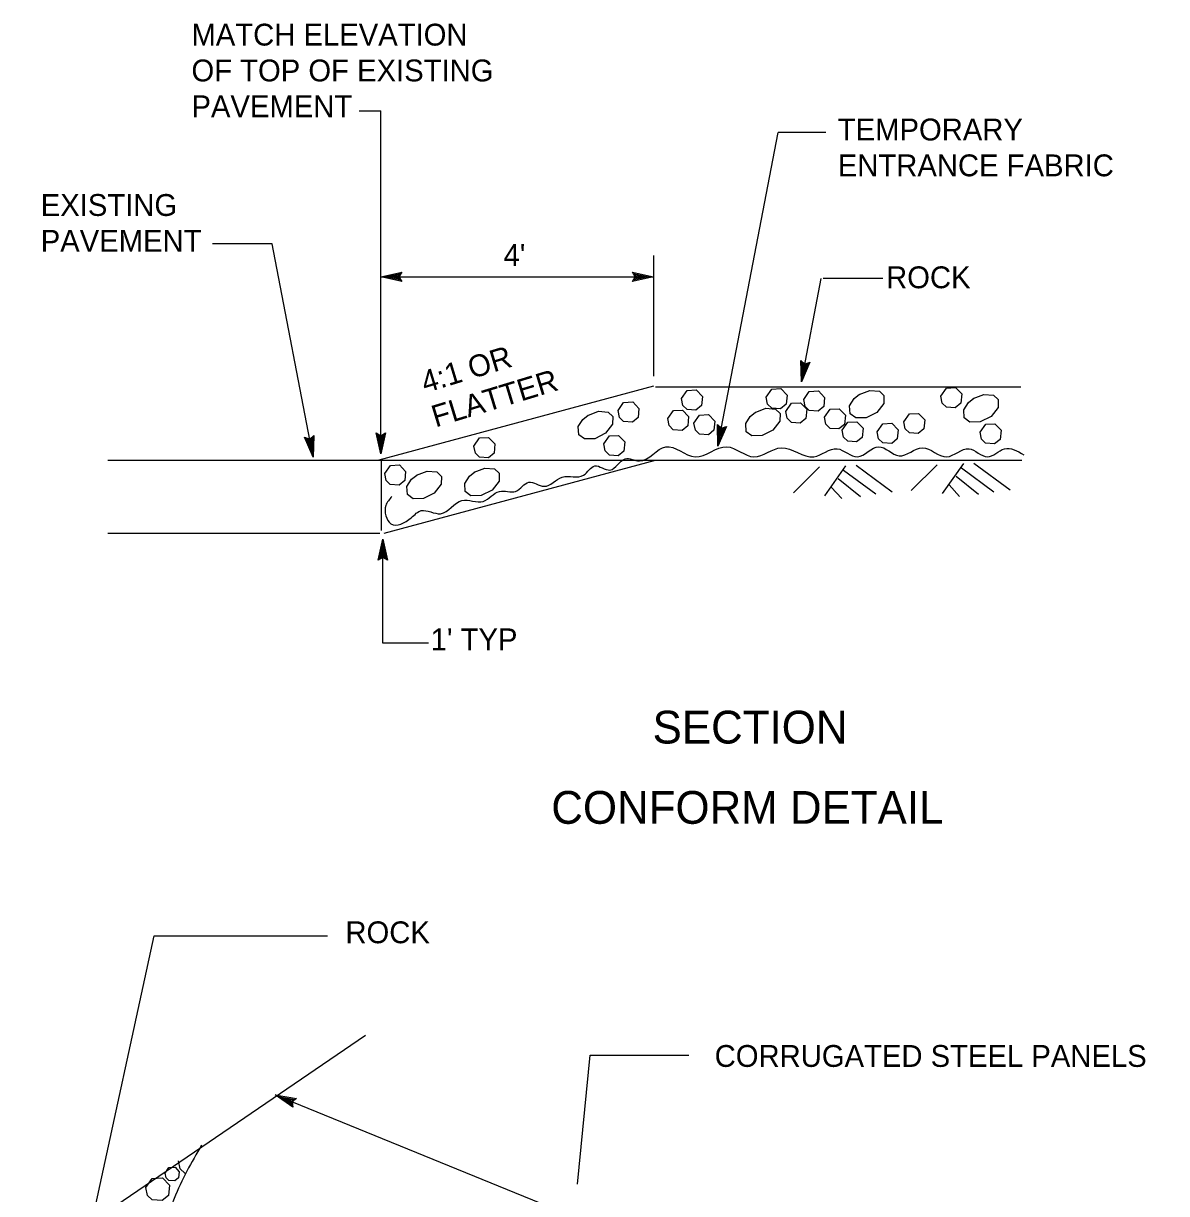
# Model space of a CAD drawing. Extents: x 6709491 to 6710959, y 1869789 to 1870763.
# Drawn here: x 6709790.5 to 6710104.3, y 1870437.5 to 1870758.8 of the extents above; entities that cross this region are included whole.
import ezdxf

# ---------------------------------------------------------------- set-up
doc = ezdxf.new("R2010")
doc.units = 0
for name, color, linetype in [('56 Stg 3 Anno', 7, 'Continuous'), ('57 Undefined', 7, 'Continuous'), ('59 Soundwall Ann', 7, 'Continuous'), ('60 Nongeo Data', 7, 'Continuous')]:
    doc.layers.add(name, color=color, linetype=linetype)

msp = doc.modelspace()

# ---------------------------------------------------------------- linework, layer by layer
at = {"layer": '56 Stg 3 Anno'}
for p, q in [((6709882.69, 1870734.85), (6709888.58, 1870734.85)), ((6709888.58, 1870640.62), (6709888.58, 1870734.85)), ((6709981.16, 1870642.76), (6709997.7, 1870728.84)), ((6710010.8, 1870728.84), (6709997.7, 1870728.84)), ((6709858.77, 1870698.25), (6709842.43, 1870698.25)), ((6709870.01, 1870639.76), (6709858.77, 1870698.25)), ((6709963.41, 1870695.06), (6709963.41, 1870661.92)), ((6709888.58, 1870689.24), (6709894.34, 1870690.52)), ((6709889.92, 1870689.24), (6709894.12, 1870690.17)), ((6709894.34, 1870690.52), (6709893.58, 1870689.24)), ((6709894.34, 1870690.52), (6709894.34, 1870690.52)), ((6709958.42, 1870689.24), (6709957.65, 1870690.53)), ((6709957.65, 1870690.53), (6709957.65, 1870690.53)), ((6709957.65, 1870690.53), (6709963.41, 1870689.24)), ((6709957.86, 1870690.19), (6709962.09, 1870689.24)), ((6709888.58, 1870689.24), (6709963.41, 1870689.24)), ((6709894.34, 1870687.95), (6709888.58, 1870689.24)), ((6709888.58, 1870689.24), (6709888.58, 1870689.24)), ((6709894.14, 1870688.3), (6709889.91, 1870689.24)), ((6709891.24, 1870689.24), (6709893.95, 1870689.84)), ((6709893.91, 1870688.64), (6709891.24, 1870689.24)), ((6709892.56, 1870689.24), (6709893.72, 1870689.49)), ((6709893.74, 1870688.97), (6709892.56, 1870689.24)), ((6709893.58, 1870689.24), (6709894.34, 1870687.95)), ((6709894.34, 1870687.95), (6709894.34, 1870687.95)), ((6709963.41, 1870689.24), (6709957.65, 1870687.96)), ((6709957.65, 1870687.96), (6709958.42, 1870689.24)), ((6709957.65, 1870687.96), (6709957.65, 1870687.96)), ((6709962.08, 1870689.24), (6709957.88, 1870688.31)), ((6709960.76, 1870689.24), (6709958.05, 1870688.64)), ((6709958.09, 1870689.84), (6709960.76, 1870689.24)), ((6709958.26, 1870689.51), (6709959.44, 1870689.24)), ((6709959.44, 1870689.24), (6709958.27, 1870688.99)), ((6709963.41, 1870689.24), (6709963.41, 1870689.24)), ((6710004.04, 1870660.38), (6710009.5, 1870688.77)), ((6710026.4, 1870688.77), (6710010.05, 1870688.77)), ((6710004.04, 1870660.38), (6710003.87, 1870666.28)), ((6710003.87, 1870666.28), (6710003.87, 1870666.28)), ((6710003.87, 1870666.28), (6710004.98, 1870665.28)), ((6710006.39, 1870665.79), (6710004.04, 1870660.38)), ((6710004.29, 1870661.69), (6710004.17, 1870665.99)), ((6710006.02, 1870665.65), (6710004.29, 1870661.68)), ((6710004.54, 1870662.98), (6710004.46, 1870665.76)), ((6710005.63, 1870665.5), (6710004.54, 1870662.98)), ((6710004.79, 1870664.28), (6710004.76, 1870665.47)), ((6710005.28, 1870665.39), (6710004.79, 1870664.28)), ((6710004.98, 1870665.28), (6710006.39, 1870665.79)), ((6710006.39, 1870665.79), (6710006.39, 1870665.79)), ((6710004.04, 1870660.38), (6710004.04, 1870660.38)), ((6709981.16, 1870642.76), (6709981, 1870648.65)), ((6709981, 1870648.65), (6709981, 1870648.65)), ((6709981, 1870648.65), (6709982.1, 1870647.66)), ((6709981.41, 1870644.07), (6709981.29, 1870648.37)), ((6709870.01, 1870639.76), (6709867.67, 1870645.17)), ((6709867.67, 1870645.17), (6709867.67, 1870645.17)), ((6709867.67, 1870645.17), (6709869.07, 1870644.66)), ((6709869.07, 1870644.66), (6709870.19, 1870645.66)), ((6709869.59, 1870645.1), (6709869.51, 1870642.36)), ((6709869.89, 1870645.39), (6709869.76, 1870641.06)), ((6709870.19, 1870645.66), (6709870.01, 1870639.76)), ((6709870.19, 1870645.66), (6709870.19, 1870645.66)), ((6709888.58, 1870640.62), (6709887.31, 1870646.38)), ((6709887.31, 1870646.38), (6709887.31, 1870646.38)), ((6709887.31, 1870646.38), (6709888.58, 1870645.61)), ((6709888.58, 1870641.95), (6709887.65, 1870646.15)), ((6709888.59, 1870643.27), (6709887.98, 1870645.98)), ((6709888.59, 1870644.6), (6709888.33, 1870645.76)), ((6709888.58, 1870645.61), (6709889.87, 1870646.38)), ((6709889.87, 1870646.38), (6709888.58, 1870640.62)), ((6709889.53, 1870646.17), (6709888.58, 1870641.94)), ((6709889.18, 1870645.94), (6709888.59, 1870643.27)), ((6709888.85, 1870645.78), (6709888.59, 1870644.6)), ((6709889.87, 1870646.38), (6709889.87, 1870646.38)), ((6709983.51, 1870648.17), (6709981.16, 1870642.76)), ((6709983.14, 1870648.03), (6709981.41, 1870644.06)), ((6709981.67, 1870645.36), (6709981.59, 1870648.14)), ((6709982.76, 1870647.88), (6709981.67, 1870645.36)), ((6709981.92, 1870646.66), (6709981.88, 1870647.85)), ((6709982.4, 1870647.77), (6709981.92, 1870646.66)), ((6709982.1, 1870647.66), (6709983.51, 1870648.17)), ((6709983.51, 1870648.17), (6709983.51, 1870648.17)), ((6709869.76, 1870641.07), (6709868.05, 1870645.02)), ((6709869.51, 1870642.36), (6709868.41, 1870644.91)), ((6709869.26, 1870643.67), (6709868.79, 1870644.76)), ((6709869.3, 1870644.88), (6709869.26, 1870643.67)), ((6709981.16, 1870642.76), (6709981.16, 1870642.76)), ((6709870.01, 1870639.76), (6709870.01, 1870639.76)), ((6709888.58, 1870640.62), (6709888.58, 1870640.62)), ((6709887.85, 1870611.42), (6709889.14, 1870617.18)), ((6709889.14, 1870588.65), (6709889.14, 1870617.18)), ((6709889.14, 1870617.18), (6709889.14, 1870617.18)), ((6709889.14, 1870617.18), (6709890.42, 1870611.42)), ((6709888.2, 1870611.63), (6709889.14, 1870615.86)), ((6709888.54, 1870611.86), (6709889.14, 1870614.53)), ((6709888.87, 1870612.03), (6709889.14, 1870613.21)), ((6709889.14, 1870615.85), (6709890.07, 1870611.65)), ((6709889.14, 1870614.53), (6709889.74, 1870611.82)), ((6709889.14, 1870613.21), (6709889.39, 1870612.05)), ((6709889.14, 1870612.19), (6709887.85, 1870611.42)), ((6709887.85, 1870611.42), (6709887.85, 1870611.42)), ((6709890.42, 1870611.42), (6709889.14, 1870612.19)), ((6709890.42, 1870611.42), (6709890.42, 1870611.42)), ((6709901.67, 1870588.65), (6709889.14, 1870588.65)), ((6709803.25, 1870401.82), (6709826.34, 1870508.28)), ((6709826.34, 1870508.28), (6709873.95, 1870508.28)), ((6709942.55, 1870440.07), (6709946.04, 1870475.53)), ((6709946.04, 1870475.53), (6709973.16, 1870475.53)), ((6709859.63, 1870464.61), (6710181.3, 1870333.54)), ((6709864.48, 1870461.25), (6709859.63, 1870464.61)), ((6709859.63, 1870464.61), (6709859.63, 1870464.61)), ((6709859.63, 1870464.61), (6709865.45, 1870463.62)), ((6709864.42, 1870461.64), (6709860.86, 1870464.11)), ((6709860.87, 1870464.11), (6709865.11, 1870463.39)), ((6709864.34, 1870462.05), (6709862.09, 1870463.61)), ((6709862.09, 1870463.61), (6709864.83, 1870463.14)), ((6709864.31, 1870462.42), (6709863.32, 1870463.11)), ((6709863.32, 1870463.11), (6709864.49, 1870462.91)), ((6709865.45, 1870463.62), (6709864.26, 1870462.73)), ((6709864.26, 1870462.73), (6709864.48, 1870461.25)), ((6709865.45, 1870463.62), (6709865.45, 1870463.62)), ((6709864.48, 1870461.25), (6709864.48, 1870461.25))]:
    msp.add_line(p, q, dxfattribs=at)
at = {"layer": '59 Soundwall Ann'}
for p, q in [((6710009.02, 1870637.04), (6710001.85, 1870629.93)), ((6710016.17, 1870637.38), (6710010.38, 1870629.14)), ((6710015.62, 1870636.16), (6710024.52, 1870629.61)), ((6710019.07, 1870637.51), (6710029.02, 1870630.18)), ((6710041.37, 1870637.64), (6710034.2, 1870630.53)), ((6710048.52, 1870637.98), (6710042.74, 1870629.74)), ((6710047.97, 1870636.76), (6710056.87, 1870630.21)), ((6710051.42, 1870638.11), (6710061.38, 1870630.78)), ((6710014.18, 1870633.9), (6710020.29, 1870628.92)), ((6710046.53, 1870634.5), (6710052.64, 1870629.52)), ((6710012.24, 1870631.52), (6710015.15, 1870628.32)), ((6710044.59, 1870632.11), (6710047.5, 1870628.92))]:
    msp.add_line(p, q, dxfattribs=at)
at = {"layer": '60 Nongeo Data'}
for p, q in [((6709888.11, 1870638.95), (6709963.56, 1870659.27)), ((6709964.03, 1870658.99), (6710064.27, 1870658.99)), ((6709813.68, 1870638.93), (6709888.86, 1870638.93)), ((6709888.67, 1870638.97), (6709888.67, 1870619.57)), ((6709888.86, 1870638.93), (6709964.59, 1870638.93)), ((6709889.53, 1870618.87), (6709964.03, 1870638.93)), ((6709964.03, 1870638.93), (6710064.55, 1870638.93)), ((6709813.68, 1870618.87), (6709888.3, 1870618.87)), ((6709495.94, 1870216.26), (6709884.38, 1870481.01))]:
    msp.add_line(p, q, dxfattribs=at)
for points in [[(6709971.13, 1870655.85), (6709972.68, 1870658.05), (6709975.15, 1870658.19), (6709976.87, 1870656.41), (6709976.62, 1870653.91), (6709975.1, 1870652.64), (6709972.65, 1870652.82), (6709971.5, 1870653.93), (6709971.13, 1870655.85)], [(6709994.38, 1870656.22), (6709995.93, 1870658.43), (6709998.41, 1870658.57), (6710000.13, 1870656.78), (6709999.88, 1870654.28), (6709998.35, 1870653.01), (6709995.91, 1870653.19), (6709994.76, 1870654.3), (6709994.39, 1870656.22)], [(6710019.9, 1870656.91), (6710022.8, 1870658.05), (6710025.46, 1870657.82), (6710026.73, 1870656.62), (6710026.69, 1870654.46), (6710024.77, 1870652), (6710021.8, 1870650.52), (6710019, 1870650.47), (6710017.42, 1870651.59), (6710017.27, 1870653.82), (6710018.55, 1870655.81), (6710020.02, 1870656.98)], [(6710042.34, 1870656.49), (6710043.89, 1870658.7), (6710046.36, 1870658.84), (6710048.08, 1870657.06), (6710047.84, 1870654.55), (6710046.31, 1870653.28), (6710043.86, 1870653.46), (6710042.71, 1870654.58), (6710042.34, 1870656.49)], [(6709953.71, 1870652.52), (6709955.26, 1870654.73), (6709957.74, 1870654.87), (6709959.46, 1870653.09), (6709959.21, 1870650.59), (6709957.68, 1870649.31), (6709955.23, 1870649.49), (6709954.08, 1870650.61), (6709953.71, 1870652.52)], [(6710004.68, 1870655.56), (6710006.23, 1870657.76), (6710008.71, 1870657.9), (6710010.43, 1870656.12), (6710010.18, 1870653.62), (6710008.65, 1870652.35), (6710006.21, 1870652.52), (6710005.06, 1870653.64), (6710004.68, 1870655.55)], [(6710051.24, 1870655.8), (6710054.14, 1870656.95), (6710056.8, 1870656.72), (6710058.07, 1870655.51), (6710058.03, 1870653.35), (6710056.11, 1870650.9), (6710053.14, 1870649.41), (6710050.34, 1870649.36), (6710048.76, 1870650.48), (6710048.62, 1870652.71), (6710049.89, 1870654.7), (6710051.36, 1870655.87)], [(6709945.44, 1870651.18), (6709948.34, 1870652.33), (6709951, 1870652.09), (6709952.27, 1870650.89), (6709952.23, 1870648.73), (6709950.3, 1870646.27), (6709947.33, 1870644.79), (6709944.54, 1870644.74), (6709942.96, 1870645.86), (6709942.81, 1870648.09), (6709944.09, 1870650.08), (6709945.55, 1870651.25)], [(6709967.35, 1870650.29), (6709968.9, 1870652.5), (6709971.38, 1870652.64), (6709973.1, 1870650.86), (6709972.85, 1870648.36), (6709971.32, 1870647.08), (6709968.88, 1870647.26), (6709967.73, 1870648.38), (6709967.36, 1870650.29)], [(6709991.38, 1870652.01), (6709994.28, 1870653.16), (6709996.94, 1870652.93), (6709998.21, 1870651.73), (6709998.17, 1870649.57), (6709996.25, 1870647.11), (6709993.28, 1870645.62), (6709990.48, 1870645.58), (6709988.9, 1870646.69), (6709988.76, 1870648.92), (6709990.03, 1870650.92), (6709991.5, 1870652.09)], [(6709999.79, 1870652.29), (6710001.34, 1870654.5), (6710003.82, 1870654.64), (6710005.54, 1870652.86), (6710005.29, 1870650.36), (6710003.76, 1870649.08), (6710001.32, 1870649.26), (6710000.17, 1870650.38), (6709999.79, 1870652.29)], [(6710010.39, 1870650.66), (6710011.94, 1870652.87), (6710014.41, 1870653.01), (6710016.13, 1870651.22), (6710015.88, 1870648.72), (6710014.35, 1870647.45), (6710011.91, 1870647.63), (6710010.76, 1870648.75), (6710010.39, 1870650.66)], [(6710032.17, 1870649.41), (6710033.73, 1870651.61), (6710036.2, 1870651.75), (6710037.92, 1870649.97), (6710037.67, 1870647.47), (6710036.14, 1870646.2), (6710033.7, 1870646.37), (6710032.55, 1870647.49), (6710032.18, 1870649.4)], [(6709974.57, 1870649.07), (6709976.12, 1870651.28), (6709978.59, 1870651.42), (6709980.31, 1870649.64), (6709980.06, 1870647.13), (6709978.54, 1870645.86), (6709976.09, 1870646.04), (6709974.94, 1870647.16), (6709974.57, 1870649.07)], [(6710015.24, 1870647.1), (6710016.79, 1870649.31), (6710019.27, 1870649.45), (6710020.98, 1870647.66), (6710020.74, 1870645.16), (6710019.21, 1870643.89), (6710016.76, 1870644.07), (6710015.61, 1870645.18), (6710015.24, 1870647.1)], [(6710024.88, 1870646.67), (6710026.43, 1870648.87), (6710028.9, 1870649.02), (6710030.62, 1870647.23), (6710030.37, 1870644.73), (6710028.85, 1870643.46), (6710026.4, 1870643.64), (6710025.25, 1870644.75), (6710024.88, 1870646.67)], [(6710053.12, 1870646.55), (6710054.67, 1870648.75), (6710057.14, 1870648.9), (6710058.86, 1870647.11), (6710058.62, 1870644.61), (6710057.09, 1870643.34), (6710054.64, 1870643.52), (6710053.49, 1870644.63), (6710053.12, 1870646.55)], [(6709914.17, 1870642.77), (6709915.72, 1870644.98), (6709918.2, 1870645.12), (6709919.92, 1870643.33), (6709919.67, 1870640.83), (6709918.14, 1870639.56), (6709915.69, 1870639.74), (6709914.55, 1870640.85), (6709914.17, 1870642.77)], [(6709949.81, 1870643.33), (6709951.36, 1870645.53), (6709953.84, 1870645.67), (6709955.56, 1870643.89), (6709955.31, 1870641.39), (6709953.78, 1870640.12), (6709951.34, 1870640.3), (6709950.19, 1870641.41), (6709949.81, 1870643.33)], [(6709889.67, 1870635.25), (6709891.22, 1870637.45), (6709893.69, 1870637.59), (6709895.41, 1870635.81), (6709895.16, 1870633.31), (6709893.64, 1870632.04), (6709891.19, 1870632.22), (6709890.04, 1870633.33), (6709889.67, 1870635.25)], [(6709898.38, 1870634.74), (6709901.28, 1870635.89), (6709903.94, 1870635.66), (6709905.21, 1870634.45), (6709905.17, 1870632.29), (6709903.25, 1870629.83), (6709900.28, 1870628.35), (6709897.48, 1870628.3), (6709895.9, 1870629.42), (6709895.76, 1870631.65), (6709897.03, 1870633.64), (6709898.5, 1870634.81)], [(6709914.25, 1870635.57), (6709917.15, 1870636.72), (6709919.82, 1870636.49), (6709921.08, 1870635.29), (6709921.04, 1870633.13), (6709919.12, 1870630.67), (6709916.15, 1870629.19), (6709913.35, 1870629.14), (6709911.78, 1870630.26), (6709911.63, 1870632.48), (6709912.9, 1870634.48), (6709914.37, 1870635.65)], [(6709834.9, 1870443.07), (6709834.76, 1870443.08), (6709833.47, 1870444.33), (6709833.05, 1870446.48)], [(6709829.39, 1870443.15), (6709830.43, 1870444.64), (6709832.1, 1870444.73), (6709833.25, 1870443.53), (6709833.09, 1870441.85), (6709832.06, 1870440.99), (6709830.41, 1870441.11), (6709829.64, 1870441.86), (6709829.39, 1870443.15)], [(6709824.11, 1870439.17), (6709825.85, 1870441.64), (6709828.62, 1870441.8), (6709830.56, 1870439.8), (6709830.28, 1870437), (6709828.56, 1870435.57), (6709825.82, 1870435.77), (6709824.53, 1870437.02), (6709824.11, 1870439.17)]]:
    msp.add_lwpolyline(points, dxfattribs=at)
for points in [[(6709891.64, 1870628.94), (6709889.97, 1870626.43), (6709889.97, 1870623.64), (6709891.36, 1870621.42), (6709896.93, 1870623.09), (6709899.71, 1870625.04), (6709905.01, 1870624.2), (6709910.85, 1870627.82), (6709916.7, 1870627.55), (6709921.15, 1870630.33), (6709925.61, 1870630.33), (6709929.23, 1870632.84), (6709933.41, 1870631.72), (6709938.42, 1870634.23), (6709944.27, 1870634.79), (6709947.33, 1870637.3), (6709951.51, 1870636.18), (6709955.68, 1870639.25), (6709959.58, 1870638.69), (6709966.82, 1870642.59), (6709974.89, 1870639.81), (6709983.53, 1870642.59), (6709991.04, 1870639.81), (6709998.56, 1870642.31), (6710007.47, 1870639.81), (6710013.88, 1870642.03), (6710019.44, 1870639.81), (6710025.29, 1870642.59), (6710030.86, 1870640.08), (6710037.27, 1870642.31), (6710043.95, 1870639.81), (6710050.07, 1870642.03), (6710055.09, 1870639.81), (6710059.82, 1870642.03), (6710065.11, 1870640.36)], [(6709839.39, 1870450.83), (6709831.86, 1870436.12), (6709837.31, 1870381.57), (6709845.79, 1870371.27)]]:
    msp.add_spline(points, degree=3, dxfattribs=at)

# ---------------------------------------------------------------- texts
at = {"layer": '57 Undefined'}
for s, height, p in [('MATCH ELEVATION', 6, (6709836.61, 1870752.73)), ('OF TOP OF EXISTING ', 6, (6709836.61, 1870742.89)), ('PAVEMENT', 6, (6709836.61, 1870733.05)), ('TEMPORARY', 6, (6710014.05, 1870726.68)), ('ENTRANCE FABRIC', 6, (6710014.05, 1870716.84)), ('EXISTING', 6, (6709795.23, 1870705.95)), ('PAVEMENT', 6, (6709795.23, 1870696.11)), ("4'", 6, (6709922.29, 1870692.24)), ('ROCK', 6, (6710027.31, 1870686.1)), ("1' TYP", 6, (6709902.28, 1870586.69)), ('SECTION', 9, (6709963.21, 1870561.09)), ('CONFORM DETAIL', 9, (6709935.39, 1870539.05)), ('ROCK', 6, (6709878.88, 1870506.25)), ('CORRUGATED STEEL PANELS', 6, (6709980.25, 1870472.3))]:
    msp.add_text(s, height=height, dxfattribs=at).set_placement(p)
for s, p in [('4:1 OR ', (6709900.77, 1870657.28)), ('FLATTER', (6709903.63, 1870647.86))]:
    msp.add_text(s, height=6, rotation=16.9097, dxfattribs=at).set_placement(p)

doc.saveas('drawing.dxf')
